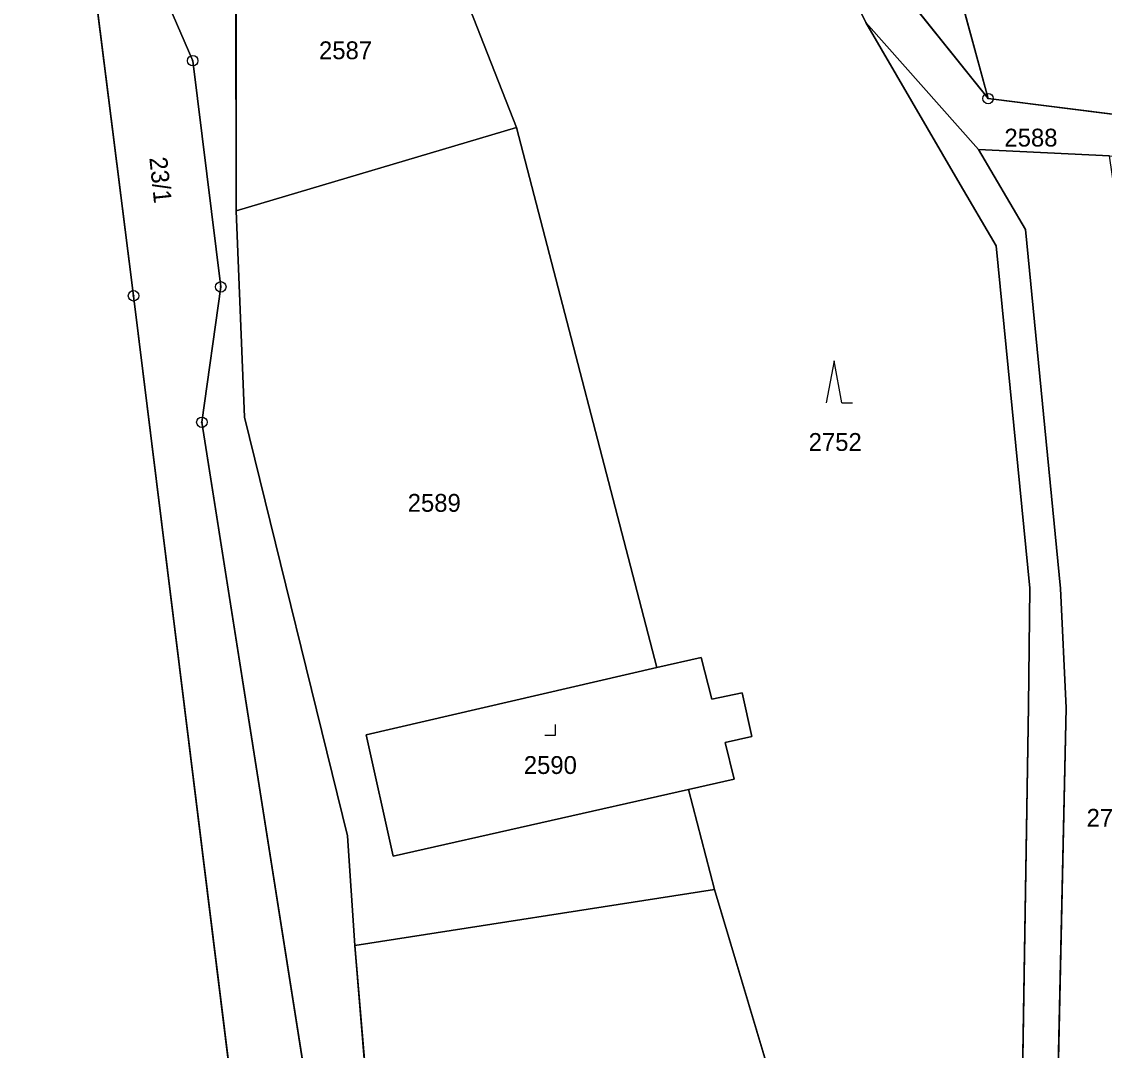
# Model space of a CAD drawing. Extents: x -689422 to -685210, y -987725 to -982160.
# Drawn here: x -687134.4 to -687031.2, y -986808.7 to -986710.7 of the extents above; entities that cross this region are included whole.
import ezdxf

# ---------------------------------------------------------------- set-up
doc = ezdxf.new("R2010")
doc.units = 0
for name, color, linetype in [('KN_Hranice_parcel', 7, 'Continuous'), ('KN_Parcelni cisla', 7, 'Continuous'), ('KN_Polygon parcely', 7, 'Continuous'), ('KN_POZEMKY_LESNI POZEMEK', 7, 'Continuous'), ('KN_POZEMKY_ORNA PUDA', 7, 'Continuous'), ('KN_POZEMKY_OSTATNI PLOCHA', 7, 'Continuous'), ('KN_POZEMKY_TTP', 7, 'Continuous'), ('KN_POZEMKY_ZASTAVENA PLOCHA', 7, 'Continuous'), ('KN_VYUZITI_13_zastavena plocha_zboreniste', 7, 'Continuous'), ('KN_VYUZITI_17_ostatni plocha_ostatni komunikace', 7, 'Continuous'), ('KN_VYUZITI_26_ostatni plocha_jina plocha', 7, 'Continuous'), ('KN_VYUZITI_27_ostatni plocha_neplodna puda', 7, 'Continuous'), ('KN_Značky bodu BP', 7, 'Continuous'), ('KN_Značky kultur', 7, 'Continuous')]:
    doc.layers.add(name, color=color, linetype=linetype)

msp = doc.modelspace()

# ---------------------------------------------------------------- linework, layer by layer
at = {"layer": 'KN_Hranice_parcel'}
for p, q in [((-687053.98, -986710.73), (-687043.23, -986722.85)), ((-687113.95, -986728.67), (-687087.24, -986720.75)), ((-687073.87, -986772.21), (-687087.24, -986720.75)), ((-687043.23, -986722.85), (-687030.76, -986723.44)), ((-687068.39, -986793.35), (-687070.86, -986783.82)), ((-687102.67, -986798.7), (-687068.39, -986793.35)), ((-687102.67, -986798.7), (-687097.68, -986857.59))]:
    msp.add_line(p, q, dxfattribs=at)
for points in [[(-687080.36, -986492.73), (-687078.1, -986550.59), (-687072.97, -986615.43), (-687068.19, -986661.22), (-687065.37, -986676.32), (-687050.77, -986707.44), (-687042.33, -986717.99)], [(-687133.5, -986598.3), (-687124.79, -986663.8), (-687121.11, -986707.42), (-687118.1, -986714.38), (-687115.43, -986735.93), (-687117.23, -986748.83), (-687105.29, -986824.57), (-687100.79, -986858.01), (-687097.31, -986882.03), (-687081.8, -986952.81)], [(-687042.33, -986717.99), (-687056.98, -986663.96), (-687063.23, -986605.59)], [(-687114.53, -986811.14), (-687123.74, -986736.78), (-687132.73, -986665.38)], [(-687070.16, -986677.59), (-687065.29, -986687.25), (-687053.98, -986710.73)], [(-687087.24, -986720.75), (-687097.19, -986695.39), (-687115.28, -986694.99)], [(-687115.28, -986694.99), (-687113.98, -986707.47), (-687113.95, -986728.67)], [(-687040.45, -986878.33), (-687039.54, -986843.03), (-687038.48, -986775.86), (-687038.35, -986764.64), (-687041.57, -986732.02), (-687045.2, -986725.79), (-687053.98, -986710.73)], [(-686947.51, -986723.37), (-687007.66, -986722.36), (-687042.33, -986717.99)], [(-687043.23, -986722.85), (-687038.75, -986730.47), (-687035.44, -986764.68), (-687034.88, -986776.05), (-687036.37, -986843.07), (-687035.51, -986893.25)], [(-687113.95, -986728.67), (-687113.18, -986748.35), (-687103.36, -986788.22), (-687102.67, -986798.7)], [(-687070.86, -986783.82), (-687066.52, -986782.84), (-687067.37, -986779.34), (-687064.82, -986778.78), (-687065.76, -986774.62), (-687068.63, -986775.22), (-687069.67, -986771.25), (-687073.87, -986772.21)], [(-687070.86, -986783.82), (-687099.01, -986790.16), (-687101.59, -986778.6), (-687073.87, -986772.21)], [(-687097.68, -986857.59), (-687049.96, -986854.98), (-687068.39, -986793.35)]]:
    msp.add_lwpolyline(points, dxfattribs=at)
at = {"layer": 'KN_Polygon parcely'}
for points in [[(-687072.96, -986662.37), (-687070.16, -986677.59), (-687065.29, -986687.25), (-687053.98, -986710.73), (-687043.23, -986722.85), (-687030.76, -986723.44), (-687007.67, -986726.07), (-687002, -986726.19), (-686947.45, -986727.38), (-686947.51, -986723.37), (-687007.66, -986722.36), (-687042.33, -986717.99), (-687050.77, -986707.44), (-687065.37, -986676.32), (-687068.19, -986661.22), (-687072.97, -986615.43), (-687078.1, -986550.59), (-687080.36, -986492.73), (-687080.7, -986488.8), (-687087.09, -986434.31), (-687093.11, -986413.86), (-687085.25, -986493.64), (-687079.74, -986616.2)], [(-687078.1, -986550.59), (-687072.97, -986615.43), (-687068.19, -986661.22), (-687065.37, -986676.32), (-687050.77, -986707.44), (-687042.33, -986717.99), (-687056.98, -986663.96), (-687063.23, -986605.59), (-687063.42, -986524.56), (-687066.49, -986494.06), (-687075.26, -986493.53), (-687080.36, -986492.73)], [(-686947.51, -986723.37), (-686940.51, -986723.49), (-686881.44, -986720.2), (-686866.09, -986648.24), (-686859.86, -986622.32), (-686915.66, -986618.74), (-686950.94, -986614.98), (-687000.29, -986608.91), (-687019.91, -986606.34), (-687063.23, -986605.59), (-687056.98, -986663.96), (-687042.33, -986717.99), (-687007.66, -986722.36)], [(-687132.73, -986665.38), (-687175.57, -986668.76), (-687223.16, -986676.53), (-687251.84, -986681.22), (-687260.77, -986682.68), (-687249.1, -986736.08), (-687233, -986786.07), (-687222.58, -986825.34), (-687193.41, -986820.33), (-687156.89, -986815.37), (-687149.53, -986814.63), (-687114.53, -986811.14), (-687123.74, -986736.78)], [(-687113.98, -986707.47), (-687113.95, -986728.67), (-687087.24, -986720.75), (-687097.19, -986695.39), (-687115.28, -986694.99)], [(-687073.87, -986772.21), (-687087.24, -986720.75), (-687113.95, -986728.67), (-687113.18, -986748.35), (-687103.36, -986788.22), (-687102.67, -986798.7), (-687068.39, -986793.35), (-687070.86, -986783.82), (-687099.01, -986790.16), (-687101.59, -986778.6)], [(-687035.51, -986893.25), (-687027.56, -986849.65), (-687026.39, -986843.23), (-687025.96, -986823.22), (-687024.7, -986765.1), (-687030.76, -986723.44), (-687043.23, -986722.85), (-687038.75, -986730.47), (-687035.44, -986764.68), (-687034.88, -986776.05), (-687036.37, -986843.07)], [(-687069.67, -986771.25), (-687073.87, -986772.21), (-687101.59, -986778.6), (-687099.01, -986790.16), (-687070.86, -986783.82), (-687066.52, -986782.84), (-687067.37, -986779.34), (-687064.82, -986778.78), (-687065.76, -986774.62), (-687068.63, -986775.22)], [(-687102.67, -986798.7), (-687097.68, -986857.59), (-687049.96, -986854.98), (-687068.39, -986793.35)]]:
    msp.add_lwpolyline(points, close=True, dxfattribs=at)
for points in [[(-687132.73, -986665.38), (-687123.74, -986736.78), (-687114.53, -986811.14), (-687111.79, -986825.4), (-687103.83, -986877.9), (-687103.23, -986882.95), (-687098.46, -986908.8), (-687089, -986950.57), (-687087.97, -986954.16), (-687069.86, -987042.61), (-687074.28, -987008.28), (-687078.78, -986972.92), (-687081.8, -986952.81), (-687097.31, -986882.03), (-687100.79, -986858.01), (-687105.29, -986824.57), (-687117.23, -986748.83), (-687115.43, -986735.93), (-687118.1, -986714.38), (-687121.11, -986707.42)], [(-687097.19, -986695.39), (-687087.24, -986720.75), (-687073.87, -986772.21), (-687069.67, -986771.25), (-687068.63, -986775.22), (-687065.76, -986774.62), (-687064.82, -986778.78), (-687067.37, -986779.34), (-687066.52, -986782.84), (-687070.86, -986783.82), (-687068.39, -986793.35), (-687049.96, -986854.98), (-687097.68, -986857.59), (-687097.65, -986861.02), (-687089.57, -986859.96), (-687088.88, -986889.77), (-687040.45, -986878.33), (-687039.54, -986843.03), (-687038.48, -986775.86), (-687038.35, -986764.64), (-687041.57, -986732.02), (-687045.2, -986725.79), (-687053.98, -986710.73), (-687065.29, -986687.25)], [(-687121.11, -986707.42), (-687118.1, -986714.38), (-687115.43, -986735.93), (-687117.23, -986748.83), (-687105.29, -986824.57), (-687100.79, -986858.01), (-687097.31, -986882.03), (-687081.8, -986952.81), (-687064.71, -987049.91), (-687070.74, -987007.79), (-687072.43, -986974.16), (-687079.35, -986943.19), (-687086.04, -986905.54), (-687088.88, -986889.77), (-687089.57, -986859.96), (-687097.65, -986861.02), (-687097.68, -986857.59), (-687102.67, -986798.7), (-687103.36, -986788.22), (-687113.18, -986748.35), (-687113.95, -986728.67), (-687113.98, -986707.47)], [(-687038.58, -986909.66), (-687035.51, -986893.25), (-687036.37, -986843.07), (-687034.88, -986776.05), (-687035.44, -986764.68), (-687038.75, -986730.47), (-687043.23, -986722.85), (-687053.98, -986710.73), (-687045.2, -986725.79), (-687041.57, -986732.02), (-687038.35, -986764.64), (-687038.48, -986775.86), (-687039.54, -986843.03), (-687040.45, -986878.33), (-687038.88, -986895.48), (-687041.79, -986910.66)]]:
    msp.add_lwpolyline(points, dxfattribs=at)
at = {"layer": 'KN_POZEMKY_LESNI POZEMEK'}
for p, q in [((-687065.29, -986687.25), (-687053.98, -986710.73)), ((-687087.24, -986720.75), (-687097.19, -986695.39)), ((-687053.98, -986710.73), (-687045.2, -986725.79)), ((-687073.87, -986772.21), (-687087.24, -986720.75)), ((-687045.2, -986725.79), (-687041.57, -986732.02)), ((-687041.57, -986732.02), (-687038.35, -986764.64)), ((-687038.35, -986764.64), (-687038.48, -986775.86)), ((-687069.67, -986771.25), (-687073.87, -986772.21)), ((-687068.63, -986775.22), (-687069.67, -986771.25)), ((-687065.76, -986774.62), (-687068.63, -986775.22)), ((-687064.82, -986778.78), (-687065.76, -986774.62)), ((-687038.48, -986775.86), (-687039.54, -986843.03)), ((-687067.37, -986779.34), (-687064.82, -986778.78)), ((-687066.52, -986782.84), (-687067.37, -986779.34)), ((-687070.86, -986783.82), (-687066.52, -986782.84)), ((-687068.39, -986793.35), (-687070.86, -986783.82)), ((-687049.96, -986854.98), (-687068.39, -986793.35))]:
    msp.add_line(p, q, dxfattribs=at)
at = {"layer": 'KN_POZEMKY_ORNA PUDA'}
for p, q in [((-687042.33, -986717.99), (-687056.98, -986663.96)), ((-687056.98, -986663.96), (-687042.33, -986717.99)), ((-687042.33, -986717.99), (-687050.77, -986707.44)), ((-687007.66, -986722.36), (-687042.33, -986717.99))]:
    msp.add_line(p, q, dxfattribs=at)
at = {"layer": 'KN_POZEMKY_OSTATNI PLOCHA'}
for p, q in [((-687123.74, -986736.78), (-687132.73, -986665.38)), ((-687053.98, -986710.73), (-687065.29, -986687.25)), ((-687121.11, -986707.42), (-687118.1, -986714.38)), ((-687118.1, -986714.38), (-687121.11, -986707.42)), ((-687113.98, -986707.47), (-687113.95, -986728.67)), ((-687050.77, -986707.44), (-687042.33, -986717.99)), ((-687045.2, -986725.79), (-687053.98, -986710.73)), ((-687053.98, -986710.73), (-687043.23, -986722.85)), ((-687043.23, -986722.85), (-687053.98, -986710.73)), ((-687118.1, -986714.38), (-687115.43, -986735.93)), ((-687115.43, -986735.93), (-687118.1, -986714.38)), ((-687042.33, -986717.99), (-687007.66, -986722.36)), ((-687113.95, -986728.67), (-687087.24, -986720.75)), ((-687087.24, -986720.75), (-687073.87, -986772.21)), ((-687043.23, -986722.85), (-687038.75, -986730.47)), ((-687030.76, -986723.44), (-687043.23, -986722.85)), ((-687041.57, -986732.02), (-687045.2, -986725.79)), ((-687113.18, -986748.35), (-687113.95, -986728.67)), ((-687113.95, -986728.67), (-687113.18, -986748.35)), ((-687038.75, -986730.47), (-687035.44, -986764.68)), ((-687038.35, -986764.64), (-687041.57, -986732.02)), ((-687115.43, -986735.93), (-687117.23, -986748.83)), ((-687117.23, -986748.83), (-687115.43, -986735.93)), ((-687114.53, -986811.14), (-687123.74, -986736.78)), ((-687103.36, -986788.22), (-687113.18, -986748.35)), ((-687113.18, -986748.35), (-687103.36, -986788.22)), ((-687117.23, -986748.83), (-687105.29, -986824.57)), ((-687105.29, -986824.57), (-687117.23, -986748.83)), ((-687038.48, -986775.86), (-687038.35, -986764.64)), ((-687035.44, -986764.68), (-687034.88, -986776.05)), ((-687073.87, -986772.21), (-687101.59, -986778.6)), ((-687039.54, -986843.03), (-687038.48, -986775.86)), ((-687034.88, -986776.05), (-687036.37, -986843.07)), ((-687101.59, -986778.6), (-687099.01, -986790.16)), ((-687099.01, -986790.16), (-687070.86, -986783.82)), ((-687070.86, -986783.82), (-687068.39, -986793.35)), ((-687102.67, -986798.7), (-687103.36, -986788.22)), ((-687103.36, -986788.22), (-687102.67, -986798.7)), ((-687068.39, -986793.35), (-687102.67, -986798.7)), ((-687102.67, -986798.7), (-687097.68, -986857.59))]:
    msp.add_line(p, q, dxfattribs=at)
at = {"layer": 'KN_POZEMKY_TTP'}
for p, q in [((-687132.73, -986665.38), (-687123.74, -986736.78)), ((-687097.19, -986695.39), (-687087.24, -986720.75)), ((-687113.95, -986728.67), (-687113.98, -986707.47)), ((-687087.24, -986720.75), (-687113.95, -986728.67)), ((-687038.75, -986730.47), (-687043.23, -986722.85)), ((-687043.23, -986722.85), (-687030.76, -986723.44)), ((-687035.44, -986764.68), (-687038.75, -986730.47)), ((-687123.74, -986736.78), (-687114.53, -986811.14)), ((-687034.88, -986776.05), (-687035.44, -986764.68)), ((-687036.37, -986843.07), (-687034.88, -986776.05)), ((-687102.67, -986798.7), (-687068.39, -986793.35)), ((-687068.39, -986793.35), (-687049.96, -986854.98)), ((-687097.68, -986857.59), (-687102.67, -986798.7))]:
    msp.add_line(p, q, dxfattribs=at)
at = {"layer": 'KN_POZEMKY_ZASTAVENA PLOCHA'}
for p, q in [((-687073.87, -986772.21), (-687069.67, -986771.25)), ((-687069.67, -986771.25), (-687068.63, -986775.22)), ((-687101.59, -986778.6), (-687073.87, -986772.21)), ((-687068.63, -986775.22), (-687065.76, -986774.62)), ((-687065.76, -986774.62), (-687064.82, -986778.78)), ((-687099.01, -986790.16), (-687101.59, -986778.6)), ((-687064.82, -986778.78), (-687067.37, -986779.34)), ((-687067.37, -986779.34), (-687066.52, -986782.84)), ((-687066.52, -986782.84), (-687070.86, -986783.82)), ((-687070.86, -986783.82), (-687099.01, -986790.16))]:
    msp.add_line(p, q, dxfattribs=at)
at = {"layer": 'KN_VYUZITI_13_zastavena plocha_zboreniste'}
for p, q in [((-687073.87, -986772.21), (-687069.67, -986771.25)), ((-687069.67, -986771.25), (-687068.63, -986775.22)), ((-687101.59, -986778.6), (-687073.87, -986772.21)), ((-687068.63, -986775.22), (-687065.76, -986774.62)), ((-687065.76, -986774.62), (-687064.82, -986778.78)), ((-687099.01, -986790.16), (-687101.59, -986778.6)), ((-687064.82, -986778.78), (-687067.37, -986779.34)), ((-687067.37, -986779.34), (-687066.52, -986782.84)), ((-687066.52, -986782.84), (-687070.86, -986783.82)), ((-687070.86, -986783.82), (-687099.01, -986790.16))]:
    msp.add_line(p, q, dxfattribs=at)
at = {"layer": 'KN_VYUZITI_17_ostatni plocha_ostatni komunikace'}
for p, q in [((-687123.74, -986736.78), (-687132.73, -986665.38)), ((-687053.98, -986710.73), (-687065.29, -986687.25)), ((-687121.11, -986707.42), (-687118.1, -986714.38)), ((-687050.77, -986707.44), (-687042.33, -986717.99)), ((-687045.2, -986725.79), (-687053.98, -986710.73)), ((-687053.98, -986710.73), (-687043.23, -986722.85)), ((-687043.23, -986722.85), (-687053.98, -986710.73)), ((-687118.1, -986714.38), (-687115.43, -986735.93)), ((-687042.33, -986717.99), (-687007.66, -986722.36)), ((-687043.23, -986722.85), (-687038.75, -986730.47)), ((-687030.76, -986723.44), (-687043.23, -986722.85)), ((-687041.57, -986732.02), (-687045.2, -986725.79)), ((-687038.75, -986730.47), (-687035.44, -986764.68)), ((-687038.35, -986764.64), (-687041.57, -986732.02)), ((-687115.43, -986735.93), (-687117.23, -986748.83)), ((-687114.53, -986811.14), (-687123.74, -986736.78)), ((-687117.23, -986748.83), (-687105.29, -986824.57)), ((-687038.48, -986775.86), (-687038.35, -986764.64)), ((-687035.44, -986764.68), (-687034.88, -986776.05)), ((-687039.54, -986843.03), (-687038.48, -986775.86)), ((-687034.88, -986776.05), (-687036.37, -986843.07))]:
    msp.add_line(p, q, dxfattribs=at)
at = {"layer": 'KN_VYUZITI_26_ostatni plocha_jina plocha'}
for p, q in [((-687113.95, -986728.67), (-687087.24, -986720.75)), ((-687087.24, -986720.75), (-687073.87, -986772.21)), ((-687113.18, -986748.35), (-687113.95, -986728.67)), ((-687103.36, -986788.22), (-687113.18, -986748.35)), ((-687073.87, -986772.21), (-687101.59, -986778.6)), ((-687101.59, -986778.6), (-687099.01, -986790.16)), ((-687099.01, -986790.16), (-687070.86, -986783.82)), ((-687070.86, -986783.82), (-687068.39, -986793.35)), ((-687102.67, -986798.7), (-687103.36, -986788.22)), ((-687068.39, -986793.35), (-687102.67, -986798.7))]:
    msp.add_line(p, q, dxfattribs=at)
at = {"layer": 'KN_VYUZITI_27_ostatni plocha_neplodna puda'}
for p, q in [((-687118.1, -986714.38), (-687121.11, -986707.42)), ((-687113.98, -986707.47), (-687113.95, -986728.67)), ((-687115.43, -986735.93), (-687118.1, -986714.38)), ((-687113.95, -986728.67), (-687113.18, -986748.35)), ((-687117.23, -986748.83), (-687115.43, -986735.93)), ((-687113.18, -986748.35), (-687103.36, -986788.22)), ((-687105.29, -986824.57), (-687117.23, -986748.83)), ((-687103.36, -986788.22), (-687102.67, -986798.7)), ((-687102.67, -986798.7), (-687097.68, -986857.59))]:
    msp.add_line(p, q, dxfattribs=at)
at = {"layer": 'KN_Značky bodu BP'}
for centre, radius in [((-687118.1, -986714.38), 0.5), ((-687118.1, -986714.38), 0.0303), ((-687042.33, -986717.99), 0.5), ((-687042.33, -986717.99), 0.0303), ((-687115.43, -986735.93), 0.5), ((-687115.43, -986735.93), 0.0303), ((-687123.74, -986736.78), 0.5), ((-687123.74, -986736.78), 0.0303), ((-687117.23, -986748.83), 0.5), ((-687117.23, -986748.83), 0.0303)]:
    msp.add_circle(centre, radius, dxfattribs=at)
at = {"layer": 'KN_Značky kultur'}
for p, q in [((-687057, -986742.99), (-687057.75, -986746.99)), ((-687056.25, -986746.99), (-687057, -986742.99)), ((-687056.25, -986746.99), (-687055.25, -986746.99)), ((-687083.54, -986778.63), (-687083.54, -986777.63)), ((-687084.54, -986778.63), (-687083.54, -986778.63))]:
    msp.add_line(p, q, dxfattribs=at)

# ---------------------------------------------------------------- texts
at = {"layer": 'KN_Parcelni cisla'}
for s, p in [('2587', (-687106.07, -986714.24)), ('2588', (-687040.77, -986722.56)), ('2752', (-687059.42, -986751.56)), ('2589', (-687097.62, -986757.36)), ('2590', (-687086.56, -986782.34)), ('2746', (-687032.94, -986787.37))]:
    msp.add_text(s, height=1.7, dxfattribs=at).set_placement(p)
msp.add_text('23/1', height=1.7, rotation=276, dxfattribs=at).set_placement((-687122.24, -986723.63))

doc.saveas('drawing.dxf')
